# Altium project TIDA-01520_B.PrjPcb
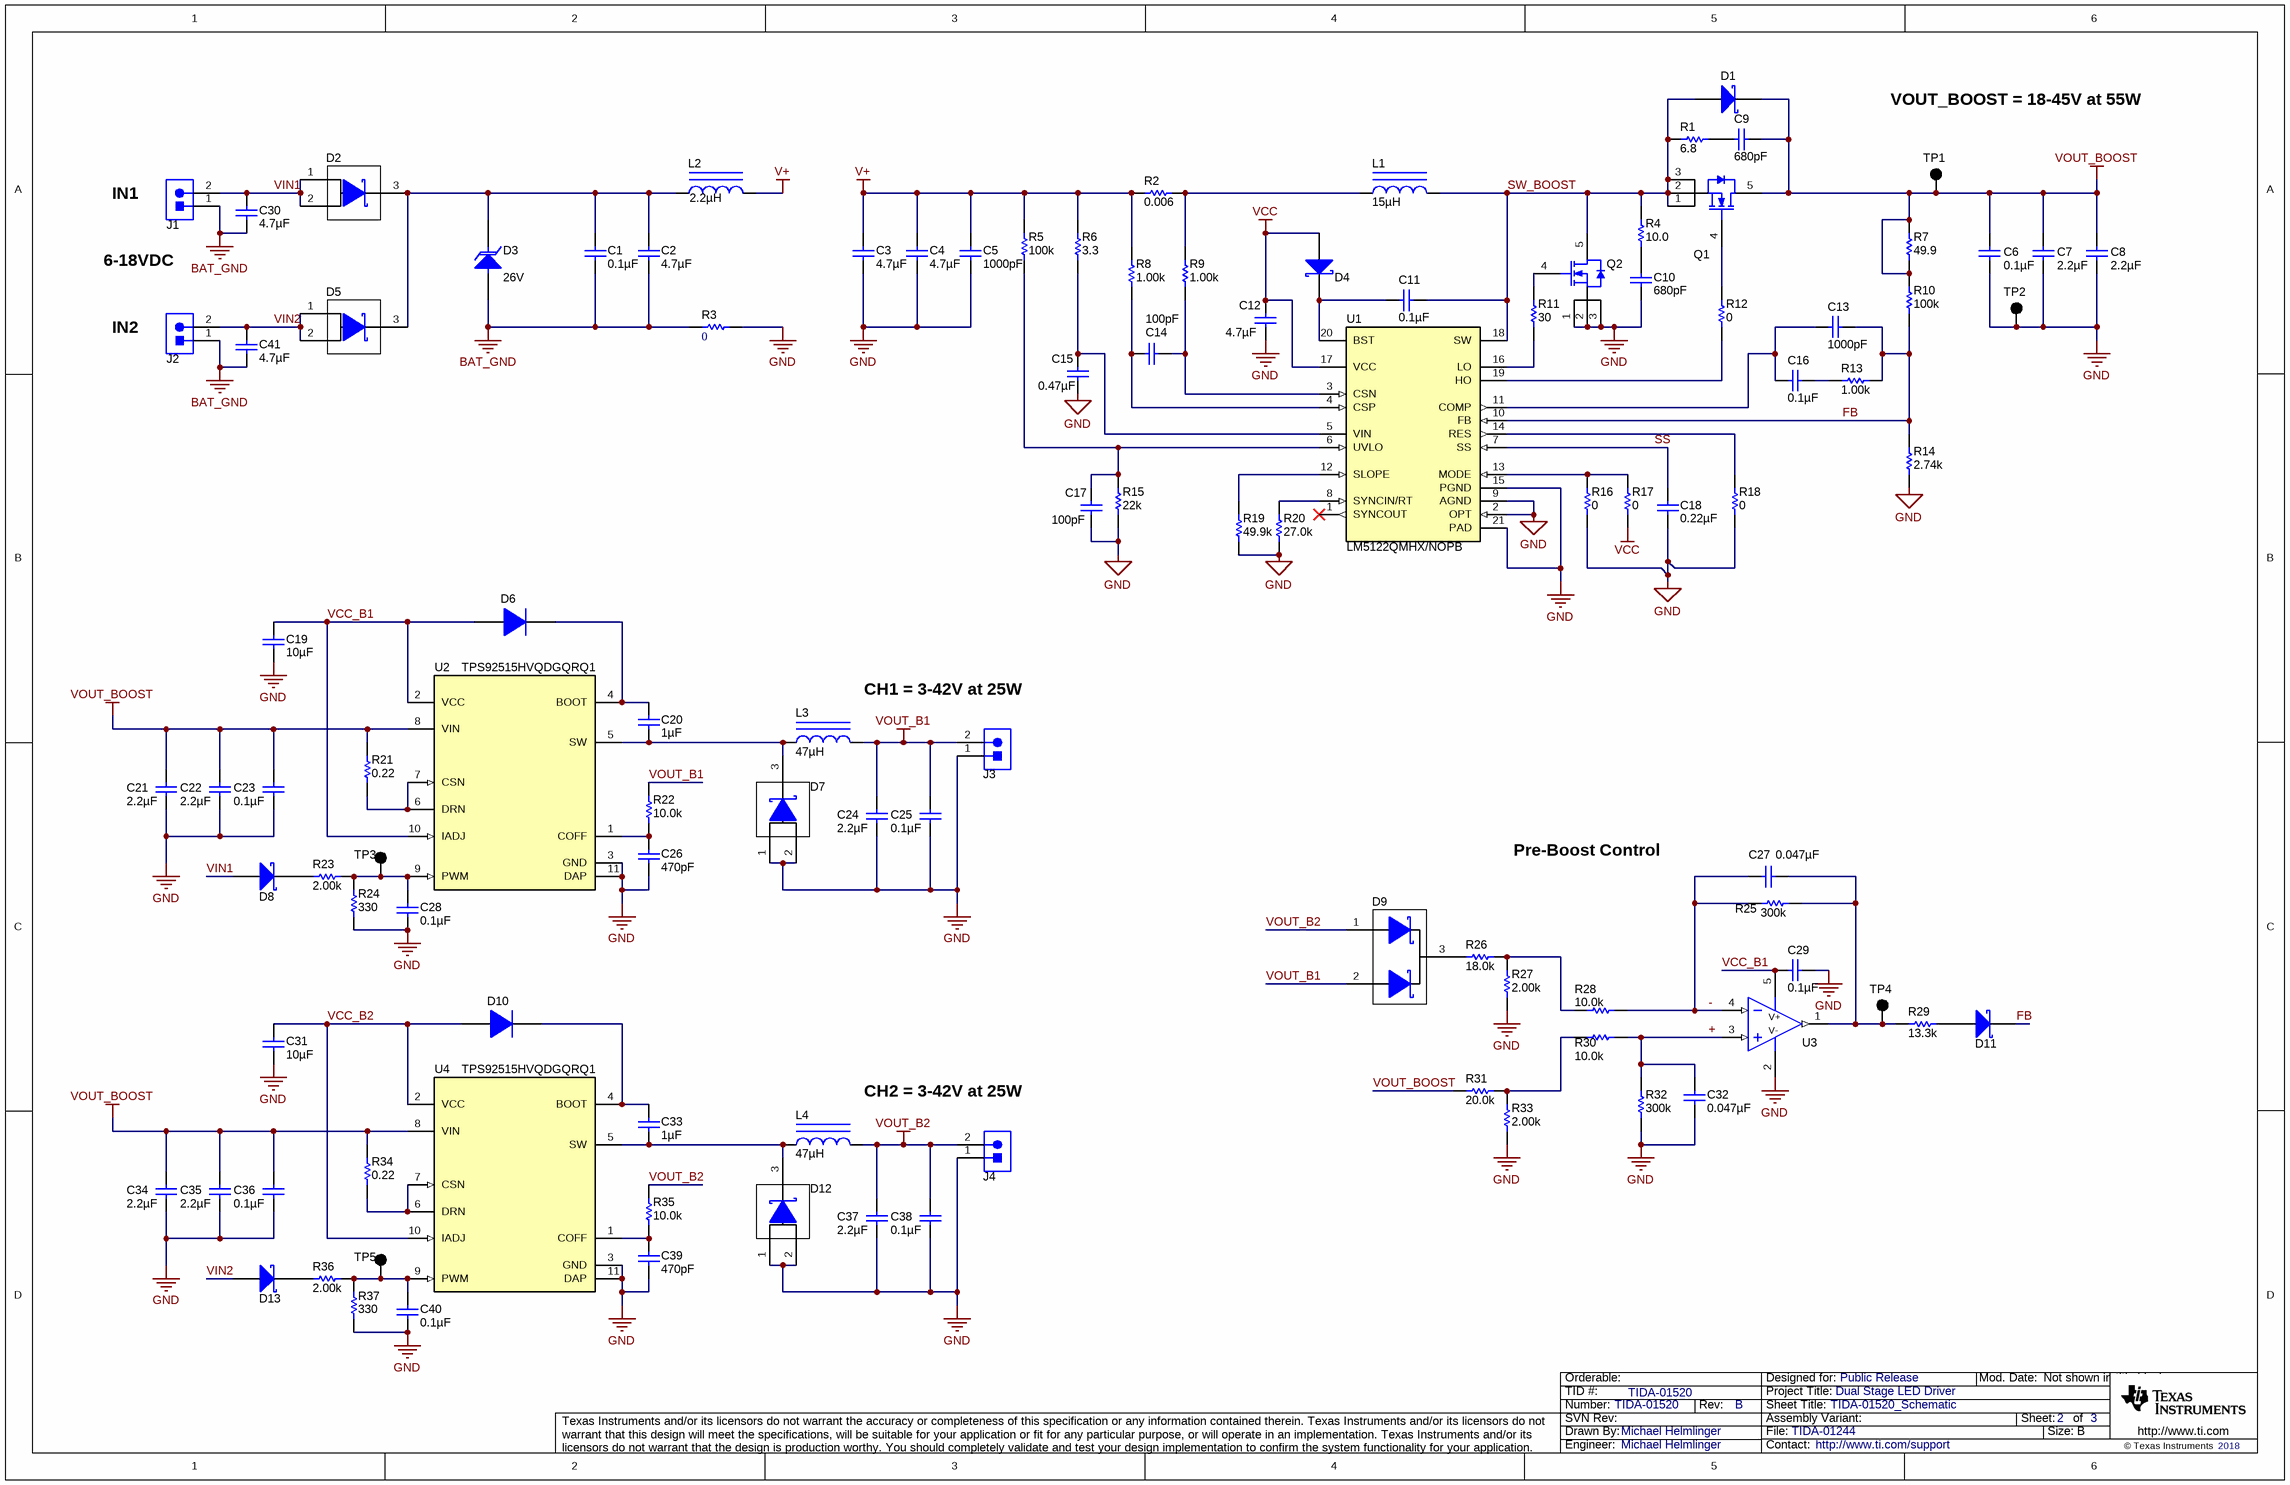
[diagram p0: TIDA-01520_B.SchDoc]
CopyrightYear: 2018; PCB_Layout: Michael Helmlinger; PCB_Rev: B; PRJ_Customer: Public Release; PRJ_Engineer: Michael Helmlinger; PRJ_Number: TIDA-01520; PRJ_Title: Dual Stage LED Driver; SCH_Rev: B; TechSupport: http://www.ti.com/support; TID: TIDA-01520
3 sheets, 119 parts. Net scope: global (net labels, ports and power ports of the same name join across sheets).
Board file: TIDA-01520_B.PcbDoc
Sheets:
  TIDA-01520_B.SchDoc
  TIDA-01520_B_Cover.SchDoc
  TIDA-01520_B_Hardware.SchDoc

## Sheet TIDA-01520_B.SchDoc: TIDA-01520_Schematic
size 431 x 279 mm; Date: Not shown in title block; ApprovedBy: Not shown in title block; CheckedBy: Not shown in title block; Author: Not shown in title block; CompanyName: Not shown in title block; DrawnBy: Michael Helmlinger; Engineer: Not shown in title block; Organization: Not shown in title block; Address1: Not shown in title block; Address2: Not shown in title block; Address3: Not shown in title block; Address4: Not shown in title block; DocumentNumber: 1; Revision: Use project parameter SCH_Rev; SheetNumber: 2; SheetTotal: 3; PageSetup: Record=PageOptions¦CenterHorizontal=True¦CenterVertical=True¦PrintScale=0.94¦XCorrection=1.00¦YCorrection=1.00¦PrintKind=0¦BorderSize=5000000¦LeftOffset=0¦BottomOffset=0¦Orientation=2¦PaperLength=4200¦PaperWidth=2970¦Scale=100¦PaperSource=7¦PrintQuality=600¦MediaType=1¦DitherType=10¦PrintScaleMode=1¦PaperKind=A3¦PaperIndex=8

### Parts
C1  ValueDisplayed: 0.1µF  [0603L]  (hidden comment: CGA3E2X7R1H104K080AA)
C2  ValueDisplayed: 4.7µF  [0805L]  (hidden comment: CGA4J3X5R1H475M125AB)
C3  ValueDisplayed: 4.7µF  [0805L]  (hidden comment: CGA4J3X5R1H475M125AB)
C4  ValueDisplayed: 4.7µF  [0805L]  (hidden comment: CGA4J3X5R1H475M125AB)
C5  ValueDisplayed: 1000pF  [0603L]  (hidden comment: CGA3E2X7R2A102K080AA)
C6  ValueDisplayed: 0.1µF  [0603L]  (hidden comment: CGA3E3X7S2A104K080AB)
C7  ValueDisplayed: 2.2µF  [1206_180]  (hidden comment: CGA5L3X7S2A225K160AB)
C8  ValueDisplayed: 2.2µF  [1206_180]  (hidden comment: CGA5L3X7S2A225K160AB)
C9  ValueDisplayed: 680pF  [0805L]  (hidden comment: GRM216R71E681KA01D)
C10  ValueDisplayed: 680pF  [0805L]  (hidden comment: GRM2165C2A681JA01D)
C11  ValueDisplayed: 0.1µF  [0603L]  (hidden comment: CGA3E2X7R1H104K080AA)
C12  ValueDisplayed: 4.7µF  [0805_HV1]  (hidden comment: GCM21BR71C475KA73L)
C13  ValueDisplayed: 1000pF  [0603L]  (hidden comment: CGA3E2X7R2A102K080AA)
C14  ValueDisplayed: 100pF  [0603L]  (hidden comment: CGA3E2NP01H101J080AA)
C15  ValueDisplayed: 0.47µF  [0603L]  (hidden comment: CGA3E3X7R1H474K080AE)
C16  ValueDisplayed: 0.1µF  [0603L]  (hidden comment: CGA3E2X7R1H104K080AA)
C17  ValueDisplayed: 100pF  [0603L]  (hidden comment: CGA3E2NP01H101J080AA)
C18  ValueDisplayed: 0.22µF  [0603L]  (hidden comment: CGA3E3X8R1E224K080AB)
C19  ValueDisplayed: 10µF  [0603L]  (hidden comment: GRM188R60J106ME84)
C20  ValueDisplayed: 1µF  [0603L]  (hidden comment: CGA3E1X7R1V105K080AC)
C21  ValueDisplayed: 2.2µF  [1206_180]  (hidden comment: CGA5L3X7S2A225K160AB)
C22  ValueDisplayed: 2.2µF  [1206_180]  (hidden comment: CGA5L3X7S2A225K160AB)
C23  ValueDisplayed: 0.1µF  [0603L]  (hidden comment: CGA3E3X7S2A104K080AB)
C24  ValueDisplayed: 2.2µF  [1206_180]  (hidden comment: CGA5L3X7S2A225K160AB)
C25  ValueDisplayed: 0.1µF  [0603L]  (hidden comment: CGA3E3X7S2A104K080AB)
C26  ValueDisplayed: 470pF  [0603L]  (hidden comment: GRM1885C1H471JA01D)
C27  ValueDisplayed: 0.047µF  [0603L]  (hidden comment: CGA3E2X7R1H473K080AA)
C28  ValueDisplayed: 0.1µF  [0603L]  (hidden comment: CGA3E2X7R1H104K080AA)
C29  ValueDisplayed: 0.1µF  [0603S]  (hidden comment: CGA3E2X7R1H104K080AA)
C30  ValueDisplayed: 4.7µF  [0805L]  (hidden comment: CGA4J3X5R1H475M125AB)
C31  ValueDisplayed: 10µF  [0603L]  (hidden comment: GRM188R60J106ME84)
C32  ValueDisplayed: 0.047µF  [0603L]  (hidden comment: CGA3E2X7R1H473K080AA)
C33  ValueDisplayed: 1µF  [0603L]  (hidden comment: CGA3E1X7R1V105K080AC)
C34  ValueDisplayed: 2.2µF  [1206_180]  (hidden comment: CGA5L3X7S2A225K160AB)
C35  ValueDisplayed: 2.2µF  [1206_180]  (hidden comment: CGA5L3X7S2A225K160AB)
C36  ValueDisplayed: 0.1µF  [0603L]  (hidden comment: CGA3E3X7S2A104K080AB)
C37  ValueDisplayed: 2.2µF  [1206_180]  (hidden comment: CGA5L3X7S2A225K160AB)
C38  ValueDisplayed: 0.1µF  [0603L]  (hidden comment: CGA3E3X7S2A104K080AB)
C39  ValueDisplayed: 470pF  [0603L]  (hidden comment: GRM1885C1H471JA01D)
C40  ValueDisplayed: 0.1µF  [0603L]  (hidden comment: CGA3E2X7R1H104K080AA)
C41  ValueDisplayed: 4.7µF  [0805L]  (hidden comment: CGA4J3X5R1H475M125AB)
D1  PMEG6010CEH,115  [SOD-123F]  (value not drawn)
D2  V12P10-M3/86A  [TO-277A]  (value not drawn)
D3  value 26V  [SMC_265]  (hidden comment: TPSMD26A)
D4  PMEG6010CEH,115  [SOD-123F]  (value not drawn)
D5  V12P10-M3/86A  [TO-277A]  (value not drawn)
D6  MMSD4148T1G  [SOD-123]  (value not drawn)
D7  PDS3100Q-13  [PowerDI5]  (value not drawn)
D8  RB520S30,115  [SOD-523]  (value not drawn)
D9  BAS70-05-7-F  [SOT-23]  (value not drawn)
D10  MMSD4148T1G  [SOD-123]  (value not drawn)
D11  RB520S30,115  [SOD-523]  (value not drawn)
D12  PDS3100Q-13  [PowerDI5]  (value not drawn)
D13  RB520S30,115  [SOD-523]  (value not drawn)
J1  1725656  [CONN_1725656]  (value not drawn)
J2  1725656  [CONN_1725656]  (value not drawn)
J3  1725656  [CONN_1725656]  (value not drawn)
J4  1725656  [CONN_1725656]  (value not drawn)
L1  ValueDisplayed: 15µH  [XAL1010]  (hidden comment: XAL1010-153MEB)
L2  ValueDisplayed: 2.2µH  [XAL5030]  (hidden comment: XAL5030-222MEB)
L3  ValueDisplayed: 47µH  [WE-PDA_1260]  (hidden comment: 784771470)
L4  ValueDisplayed: 47µH  [WE-PDA_1260]  (hidden comment: 784771470)
Q1  SQJA60EP  [PowerPAK_SO-8L]  (value not drawn)
Q2  SQJA60EP  [PowerPAK_SO-8L]  (value not drawn)
R1  ValueDisplayed: 6.8  [2010L]  (hidden comment: CRCW20106R80JNEF)
R2  ValueDisplayed: 0.006  [0612]  (hidden comment: PRL1632-R006-F-T1)
R3  ValueDisplayed: 0  [1210L]  (hidden comment: CRCW12100000Z0EA)
R4  ValueDisplayed: 10.0  [1206L]  (hidden comment: PHP01206E10R0BST5)
R5  ValueDisplayed: 100k  [0603L]  (hidden comment: CRCW0603100KJNEA)
R6  ValueDisplayed: 3.3  [0603L]  (hidden comment: CRCW06033R30JNEA)
R7  ValueDisplayed: 49.9  [0805L]  (hidden comment: CRCW080549R9FKEA)
R8  ValueDisplayed: 1.00k  [0603L]  (hidden comment: CRCW06031K00FKEA)
R9  ValueDisplayed: 1.00k  [0603L]  (hidden comment: CRCW06031K00FKEA)
R10  ValueDisplayed: 100k  [0603L]  (hidden comment: CRCW0603100KFKEA)
R11  ValueDisplayed: 30  [0603L]  (hidden comment: CRCW060330R0JNEA)
R12  ValueDisplayed: 0  [0603L]  (hidden comment: CRCW06030000Z0EA)
R13  ValueDisplayed: 1.00k  [0603L]  (hidden comment: CRCW06031K00FKEA)
R14  ValueDisplayed: 2.74k  [0603L]  (hidden comment: CRCW06032K74FKEA)
R15  ValueDisplayed: 22k  [0603L]  (hidden comment: CRCW060322K0JNEA)
R16  ValueDisplayed: 0  [0603L]  (hidden comment: CRCW06030000Z0EA)
R17  ValueDisplayed: 0  [0603L]  (hidden comment: CRCW06030000Z0EA)
R18  ValueDisplayed: 0  [0603L]  (hidden comment: CRCW06030000Z0EA)
R19  ValueDisplayed: 49.9k  [0603L]  (hidden comment: CRCW060349K9FKEA)
R20  ValueDisplayed: 27.0k  [0603L]  (hidden comment: RC0603FR-0727KL)
R21  ValueDisplayed: 0.22  [0805L]  (hidden comment: ERJ-6RQFR22V)
R22  ValueDisplayed: 10.0k  [0603L]  (hidden comment: CRCW060310K0FKEA)
R23  ValueDisplayed: 2.00k  [0603L]  (hidden comment: CRCW06032K00FKEA)
R24  ValueDisplayed: 330  [0603L]  (hidden comment: CRCW0603330RJNEA)
R25  ValueDisplayed: 300k  [0603L]  (hidden comment: CRCW0603300KFKEA)
R26  ValueDisplayed: 18.0k  [0603L]  (hidden comment: RC0603FR-0718KL)
R27  ValueDisplayed: 2.00k  [0603L]  (hidden comment: CRCW06032K00FKEA)
R28  ValueDisplayed: 10.0k  [0603L]  (hidden comment: CRCW060310K0FKEA)
R29  ValueDisplayed: 13.3k  [0603L]  (hidden comment: CRCW060313K3FKEA)
R30  ValueDisplayed: 10.0k  [0603L]  (hidden comment: CRCW060310K0FKEA)
R31  ValueDisplayed: 20.0k  [0603L]  (hidden comment: RC0603FR-0720KL)
R32  ValueDisplayed: 300k  [0603L]  (hidden comment: CRCW0603300KFKEA)
R33  ValueDisplayed: 2.00k  [0603L]  (hidden comment: CRCW06032K00FKEA)
R34  ValueDisplayed: 0.22  [0805L]  (hidden comment: ERJ-6RQFR22V)
R35  ValueDisplayed: 10.0k  [0603L]  (hidden comment: CRCW060310K0FKEA)
R36  ValueDisplayed: 2.00k  [0603L]  (hidden comment: CRCW06032K00FKEA)
R37  ValueDisplayed: 330  [0603L]  (hidden comment: CRCW0603330RJNEA)
TP1  5001  [Keystone5001]  (value not drawn)
TP2  5001  [Keystone5001]  (value not drawn)
TP3  5001  [Keystone5001]  (value not drawn)
TP4  5001  [Keystone5001]  (value not drawn)
TP5  5001  [Keystone5001]  (value not drawn)
U1  LM5122QMHX/NOPB  [PWP0020A_N]
U2  TPS92515HVQDGQRQ1  [DGQ0010E_N]
U3  OPA348AQDBVRQ1  [DBV0005A_N]  (value not drawn)
U4  TPS92515HVQDGQRQ1  [DGQ0010E_N]

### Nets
BAT_GND: C1.2 C2.2 C30.2 C41.2 D3.2(A) J1.1 J2.1 R3.1
GND: C3.2 C4.2 C5.2 C6.2 C7.2 C8.2 C10.2 C12.1 C15.2 C17.2 C18.2 C19.2 C21.2 C22.2 C23.2 C24.2 C25.2 C26.2 C28.2 C29.2 C31.2 C32.2 C34.2 C35.2 C36.2 C37.2 C38.2 C39.2 C40.2 D7.1(A) D7.2(A) D12.1(A) D12.2(A) J3.1 J4.1 Q2.1(S) Q2.2(S) Q2.3(S) R3.2 R14.2 R15.1 R16.2 R18.1 R19.1 R20.1 R24.2 R27.1 R32.1 R33.1 R37.2 TP2.1 U1.2(OPT) U1.9(AGND) U1.15(PGND) U1.21(PAD) U2.3(GND) U2.11(DAP) U3.2(V-) U4.3(GND) U4.11(DAP)
V+: C3.1 C4.1 C5.1 L2.2 R2.1 R5.2 R6.2 R8.2
VCC: C12.2 D4.2(A) R17.2 U1.17(VCC)
VOUT_B1: C24.1 C25.1 D9.2(A) J3.2 L3.2 R22.2
VOUT_B2: C37.1 C38.1 D9.1(A) J4.2 L4.2 R35.2
VOUT_BOOST: C6.1 C7.1 C8.1 C9.1 C21.1 C22.1 C23.1 C34.1 C35.1 C36.1 D1.1(K) Q1.5(D) R7.1 R7.2 R10.2 R21.2 R31.2 R34.2 TP1.1 U2.8(VIN) U4.8(VIN)
+: C32.1 R30.2 R32.2 U3.3(IN+)
-: C27.2 R25.1 R28.2 U3.4(IN-)
FB: C13.2 D11.1(K) R10.1 R13.1 R14.1 U1.10(FB)
SS: C18.1 U1.7(SS)
SW_BOOST: C11.2 D1.2(A) L1.2 Q1.1(S) Q1.2(S) Q1.3(S) Q2.5(D) R1.1 R4.2 U1.18(SW)
VCC_B1: C19.1 C29.1 D6.2(A) U2.2(VCC) U2.10(IADJ) U3.5(V+)
VCC_B2: C31.1 D10.2(A) U4.2(VCC) U4.10(IADJ)
VIN1: C30.1 D2.1(A) D2.2(A) D8.2(A) J1.2
VIN2: C41.1 D5.1(A) D5.2(A) D13.2(A) J2.2
NetC1_1: C1.1 C2.1 D2.3(K) D3.1(K) D5.3(K) L2.1
NetC9_2: C9.2 R1.2
NetC10_1: C10.1 R4.1
NetC11_1: C11.1 D4.1(K) U1.20(BST)
NetC13_1: C13.1 C16.1 U1.11(COMP)
NetC14_1: C14.1 R8.1 U1.4(CSP)
NetC14_2: C14.2 R9.1 U1.3(CSN)
NetC15_1: C15.1 R6.1 U1.5(VIN)
NetC16_2: C16.2 R13.2
NetC17_1: C17.1 R5.1 R15.2 U1.6(UVLO)
NetC20_1: C20.1 D6.1(K) U2.4(BOOT)
NetC20_2: C20.2 D7.3(K) L3.1 U2.5(SW)
NetC26_1: C26.1 R22.1 U2.1(COFF)
NetC27_1: C27.1 R25.2 R29.1 TP4.1 U3.1(OUT)
NetC28_1: C28.1 R23.1 R24.1 TP3.1 U2.9(PWM)
NetC33_1: C33.1 D10.1(K) U4.4(BOOT)
NetC33_2: C33.2 D12.3(K) L4.1 U4.5(SW)
NetC39_1: C39.1 R35.1 U4.1(COFF)
NetC40_1: C40.1 R36.1 R37.1 TP5.1 U4.9(PWM)
NetD8_1: D8.1(K) R23.2
NetD9_3: D9.3(K) R26.2
NetD11_2: D11.2(A) R29.2
NetD13_1: D13.1(K) R36.2
NetL1_1: L1.1 R2.2 R9.2
NetQ1_4: Q1.4(G) R12.2
NetQ2_4: Q2.4(G) R11.2
NetR11_1: R11.1 U1.16(LO)
NetR12_1: R12.1 U1.19(HO)
NetR16_1: R16.1 R17.1 U1.13(MODE)
NetR18_2: R18.2 U1.14(RES)
NetR19_2: R19.2 U1.12(SLOPE)
NetR20_2: R20.2 U1.8(SYNCIN/RT)
NetR21_1: R21.1 U2.6(DRN) U2.7(CSN)
NetR26_1: R26.1 R27.2 R28.1
NetR30_1: R30.1 R31.1 R33.2
NetR34_1: R34.1 U4.6(DRN) U4.7(CSN)

Not connected (* = marked no-connect by the designer): U1 1(SYNCOUT)*

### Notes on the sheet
- VOUT_BOOST = 18-45V at 55W
- IN1
- 6-18VDC
- IN2
- (near R15) 100k and 22k results in Vinstart=6.8V and Vhyst=1V
- (near R20) 27k results in 330kHz FSW
- 0.22uF results in 18ms softstart time
- CH1 = 3-42V at 25W
- Pre-Boost Control
- CH2 = 3-42V at 25W

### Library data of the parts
C1 C11 C16 C28 C29 C40 = CGA3E2X7R1H104K080AA: CAP, CERM, 0.1 µF, 50 V,+/- 10%, X7R, AEC-Q200 Grade 1, 0603; Manufacturer: TDK; Polarized: N; CompType: Capacitor; Value: 0.1uF; U/M: EA; Cap_F: 0.0000001; Tolerance_%: 10; ESR_ohm: 0.0296; Value1: 0.0296 ohm; VDC_V: 50; Value2: 50V; IRMS_A: 0.97199; TaMin_C: -55; TaMax_C: 125; Cap_Case: 0603; SizeArea_mm2: 1.28; SizeAreaWB_mm2: 4.68; SizeX_mm: 1.6; SizeY_mm: 0.8; SizeZ_mm: 1; AEC Category: Q200; AEC Qualified: Y; Green_Lifecycle: Active; Green_REACh: Passed
C2-C4 C30 C41 = CGA4J3X5R1H475M125AB: CAP, CERM, 4.7 µF, 50 V,+/- 20%, X5R, AEC-Q200 Grade 3, 0805; Manufacturer: TDK; Polarized: N; CompType: Capacitor; Value: 4.7uF; U/M: EA; Cap_F: 0.0000047; Tolerance_%: 20; VDC_V: 50; Value2: 50V; TaMin_C: -55; TaMax_C: 85; Cap_Case: 0805; SizeArea_mm2: 2.5; SizeAreaWB_mm2: 6.75; SizeX_mm: 2; SizeY_mm: 1.25; SizeZ_mm: 1.45; AEC Category: Q200; AEC Qualified: Y; AEC Grade: 3
C5 C13 = CGA3E2X7R2A102K080AA: CAP, CERM, 1000 pF, 100 V,+/- 10%, X7R, AEC-Q200 Grade 1, 0603; Manufacturer: TDK; Polarized: N; CompType: Capacitor; Value: 1000pF; U/M: EA; Cap_F: 0.000000001; Tolerance_%: 10; ESR_ohm: 1.97137; Value1: 1.97137 ohm; VDC_V: 100; Value2: 100V; IRMS_A: 0.305705; TaMin_C: -55; TaMax_C: 125; Cap_Case: 0603; SizeArea_mm2: 1.28; SizeAreaWB_mm2: 4.68; SizeX_mm: 1.6; SizeY_mm: 0.8; SizeZ_mm: 1; AEC Category: Q200; AEC Qualified: Y; Green_Lifecycle: Active; Green_REACh: Passed
C6 C23 C25 C36 C38 = CGA3E3X7S2A104K080AB: CAP, CERM, 0.1 µF, 100 V,+/- 10%, X7S, AEC-Q200 Grade 1, 0603; Manufacturer: TDK; Polarized: N; CompType: Capacitor; Value: 0.1uF; U/M: EA; Cap_F: 0.0000001; Tolerance_%: 10; ESR_ohm: 0.04959; Value1: 0.04959 ohm; VDC_V: 100; Value2: 100V; IRMS_A: 0.751618; TaMin_C: -55; TaMax_C: 125; Cap_Case: 0603; SizeArea_mm2: 1.28; SizeAreaWB_mm2: 4.68; SizeX_mm: 1.6; SizeY_mm: 0.8; SizeZ_mm: 1; AEC Category: Q200; AEC Qualified: Y
C7 C8 C21 C22 C24 C34 C35 C37 = CGA5L3X7S2A225K160AB: CAP, CERM, 2.2 µF, 100 V, +/- 10%, X7S, AEC-Q200 Grade 1, 1206; Manufacturer: TDK; Polarized: N; CompType: Capacitor; Value: 2.2uF; U/M: EA; Cap_F: 0.0000022; Tolerance_%: 10; ESR_ohm: 0.005718; Value1: 0.005718 ohm; VDC_V: 100; Value2: 100V; IRMS_A: 3.03632; TaMin_C: -55; TaMax_C: 125; SizeArea_mm2: 5.12; SizeAreaWB_mm2: 10.92; SizeX_mm: 3.2; SizeY_mm: 1.6; SizeZ_mm: 1.8; AEC Category: Q200; AEC Qualified: Y; AEC Grade: 1
C9 = GRM216R71E681KA01D: CAP, CERM, 680 pF, 25 V,+/- 10%, X7R, 0805; Manufacturer: MuRata; Polarized: N; CompType: Capacitor; Value: 680pF; U/M: EA; Cap_F: 0.00000000068; Tolerance_%: 10; VDC_V: 25; Value2: 25V; TaMin_C: -55; TaMax_C: 125; Cap_Case: 0805; SizeArea_mm2: 2.5; SizeAreaWB_mm2: 6.75; SizeX_mm: 2; SizeY_mm: 1.25; SizeZ_mm: 1.45; AEC Category: Q200
C10 = GRM2165C2A681JA01D: CAP, CERM, 680 pF, 100 V,+/- 5%, C0G/NP0, 0805; Manufacturer: MuRata; Polarized: N; CompType: Capacitor; Value: 680pF; U/M: EA; Cap_F: 0.00000000068; Tolerance_%: 5; VDC_V: 100; Value2: 100V; TaMin_C: -55; TaMax_C: 125; Cap_Case: 0805; SizeArea_mm2: 2.5; SizeAreaWB_mm2: 6.75; SizeX_mm: 2; SizeY_mm: 1.25; SizeZ_mm: 1.45; AEC Category: Q200
C12 = GCM21BR71C475KA73L: CAP, CERM, 4.7 µF, 16 V, +/- 10%, X7R, AEC-Q200 Grade 1, 0805; Manufacturer: MuRata; Polarized: N; CompType: Capacitor; Value: 4.7uF; U/M: EA; Cap_F: 0.0000047; Tolerance_%: 10; Value1: Unknown; VDC_V: 16; Value2: 16V; TaMin_C: -55; TaMax_C: 125; Cap_Case: 0805; SizeArea_mm2: 2.5; SizeAreaWB_mm2: 6.75; SizeX_mm: 2; SizeY_mm: 1.25; SizeZ_mm: 1.45; AEC Category: Q200; AEC Qualified: Y; AEC Grade: 1
C14 C17 = CGA3E2NP01H101J080AA: CAP, CERM, 100 pF, 50 V, +/- 5%, C0G/NP0, AEC-Q200 Grade 0, 0603; Manufacturer: TDK; Polarized: N; CompType: Capacitor; Value: 100pF; U/M: EA; Cap_F: 0.0000000001; Tolerance_%: 5; Value1: Unknown; VDC_V: 50; Value2: 50V; TaMin_C: -55; TaMax_C: 150; Cap_Case: 0603; SizeArea_mm2: 1.28; SizeAreaWB_mm2: 4.68; SizeX_mm: 1.6; SizeY_mm: 0.8; SizeZ_mm: 1; AEC Category: Q200; AEC Qualified: Y; AEC Grade: 0
C15 = CGA3E3X7R1H474K080AE: CAP, CERM, 0.47 µF, 50 V, +/- 10%, X7R, AEC-Q200 Grade 1, 0603; Manufacturer: TDK; Polarized: N; CompType: Capacitor; Value: 0.47uF; U/M: EA; Cap_F: 0.00000047; Tolerance_%: 10; Value1: Unknown; VDC_V: 50; Value2: 50V; TaMin_C: -55; TaMax_C: 125; Cap_Case: 0603; SizeArea_mm2: 1.28; SizeAreaWB_mm2: 4.68; SizeX_mm: 1.6; SizeY_mm: 0.8; SizeZ_mm: 1; AEC Category: Q200; AEC Qualified: Y
C18 = CGA3E3X8R1E224K080AB: CAP, CERM, 0.22 µF, 25 V,+/- 10%, X8R, AEC-Q200 Grade 0, 0603; Manufacturer: TDK; Polarized: N; CompType: Capacitor; Value: 0.22uF; U/M: EA; Cap_F: 0.00000022; Tolerance_%: 10; VDC_V: 25; Value2: 25V; TaMin_C: -55; TaMax_C: 150; Cap_Case: 0603; SizeArea_mm2: 1.28; SizeAreaWB_mm2: 4.68; SizeX_mm: 1.6; SizeY_mm: 0.8; SizeZ_mm: 1; AEC Category: Q200; AEC Qualified: Y; AEC Grade: 0
C19 C31 = GRM188R60J106ME84: CAP, CERM, 10 µF, 6.3 V,+/- 20%, X5R, 0603; Manufacturer: MuRata; Polarized: N; CompType: Capacitor; Value: 10uF; U/M: EA; Cap_F: 0.00001; Tolerance_%: 20; VDC_V: 6.3; Value2: 6.3V; TaMin_C: -55; TaMax_C: 85; Cap_Case: 0603; SizeArea_mm2: 1.28; SizeAreaWB_mm2: 4.68; SizeX_mm: 1.6; SizeY_mm: 0.8; SizeZ_mm: 1; AEC Category: Q200; Green_Lifecycle: Active; Green_REACh: Passed
C20 C33 = CGA3E1X7R1V105K080AC: CAP, CERM, 1 µF, 35 V,+/- 10%, X7R, AEC-Q200 Grade 1, 0603; Manufacturer: TDK; Polarized: N; CompType: Capacitor; Value: 1uF; U/M: EA; Cap_F: 0.000001; Tolerance_%: 10; ESR_ohm: 0.005522; Value1: 0.005522 ohm; VDC_V: 35; Value2: 35V; IRMS_A: 2.21617; TaMin_C: -55; TaMax_C: 125; Cap_Case: 0603; SizeArea_mm2: 1.28; SizeAreaWB_mm2: 4.68; SizeX_mm: 1.6; SizeY_mm: 0.8; SizeZ_mm: 1; AEC Category: Q200; AEC Qualified: Y
C26 C39 = GRM1885C1H471JA01D: CAP, CERM, 470 pF, 50 V,+/- 5%, C0G/NP0, 0603; Manufacturer: MuRata; Polarized: N; CompType: Capacitor; Value: 470pF; U/M: EA; Cap_F: 0.00000000047; Tolerance_%: 5; VDC_V: 50; Value2: 50V; TaMin_C: -55; TaMax_C: 125; Cap_Case: 0603; SizeArea_mm2: 1.28; SizeAreaWB_mm2: 4.68; SizeX_mm: 1.6; SizeY_mm: 0.8; SizeZ_mm: 1; AEC Category: Q200; Green_Lifecycle: Active; Green_REACh: Passed
C27 C32 = CGA3E2X7R1H473K080AA: CAP, CERM, 0.047 µF, 50 V,+/- 10%, X7R, AEC-Q200 Grade 1, 0603; Manufacturer: TDK; Polarized: N; CompType: Capacitor; Value: 0.047uF; U/M: EA; Cap_F: 0.000000047; Tolerance_%: 10; ESR_ohm: 0.049007; Value1: 0.049007 ohm; VDC_V: 50; Value2: 50V; IRMS_A: 0.767528; TaMin_C: -55; TaMax_C: 125; Cap_Case: 0603; SizeArea_mm2: 1.28; SizeAreaWB_mm2: 4.68; SizeX_mm: 1.6; SizeY_mm: 0.8; SizeZ_mm: 1; AEC Category: Q200; AEC Qualified: Y
D1 D4 = PMEG6010CEH,115: Diode, Schottky, 60 V, 1 A, SOD-123F; Manufacturer: Nexperia; U/M: EA; Vf_V: 0.57; Value: 60V; Value1: 1A; Value2: 0.57V; Io_A: 1; Vr_V: 60; TJmax_C: 150; SizeAreaWB_mm2: 11.7; SizeArea_mm2: 5.6; SizeX_mm: 3.5; SizeY_mm: 1.6; SizeZ_mm: 1.1; AEC Category: Q101; Green_Lifecycle: Not Set; Green_REACh: Incomplete
D2 D5 = V12P10-M3/86A: Diode, Schottky, 100 V, 12 A, AEC-Q101, TO-277A; Manufacturer: Vishay-Semiconductor; U/M: EA; Vf_V: 0.7; Value: 100V; Value1: 12A; Value2: 0.7V; Io_A: 12; Vr_V: 100; TJmax_C: 150; SizeAreaWB_mm2: 57.375; SizeArea_mm2: 30.875; SizeX_mm: 6.5; SizeY_mm: 4.75; SizeZ_mm: 1.2; AEC Category: Q101; AEC Qualified: Y; Green_Lifecycle: Not Set; Green_REACh: Incomplete
D3 = TPSMD26A: Diode, TVS, Uni, 26 V, 42.1 Vc, AEC-Q101, SMC; Manufacturer: Littelfuse; U/M: EA; Power_W: 6.5; Vr_V: 26; Value1: 6.5W; RJA_CperW: 75; SizeAreaWB_mm2: 78.5757; SizeArea_mm2: 46.8857; SizeX_mm: 7.94; SizeY_mm: 5.905; SizeZ_mm: 2.62; AEC Category: Q101; AEC Qualified: Y
D6 D10 = MMSD4148T1G: Diode, Switching, 100 V, 0.2 A, SOD-123; Manufacturer: ON Semiconductor; U/M: EA; Vf_V: 1; Value: 100V; Value1: 0.2A; Value2: 1V; Io_A: 0.2; Vr_V: 100; TJmax_C: 150; SizeAreaWB_mm2: 13.095; SizeArea_mm2: 6.545; SizeX_mm: 3.85; SizeY_mm: 1.7; SizeZ_mm: 1.35; AEC Category: Q101; Green_Lifecycle: Active; Green_REACh: Passed
D7 D12 = PDS3100Q-13: Diode, Schottky, 100 V, 3 A, AEC-Q101, PowerDI5; Manufacturer: Diodes Inc.; U/M: EA; Vf_V: 0.76; Value: 100V; Value1: 3A; Value2: 0.76V; Io_A: 3; Vr_V: 100; TJmax_C: 150; SizeAreaWB_mm2: 49.56; SizeArea_mm2: 24.96; SizeX_mm: 6.4; SizeY_mm: 3.9; SizeZ_mm: 1.05; AEC Category: Q101; AEC Qualified: Y; Green_Lifecycle: Active; Green_REACh: Passed
D8 D11 D13 = RB520S30,115: Diode, Schottky, 30 V, 0.2 A, SOD-523; Manufacturer: Nexperia; U/M: EA; Vf_V: 0.6; Value: 30V; Value1: 0.2A; Value2: 0.6V; Io_A: 0.2; Vr_V: 30; TJmax_C: 150; SizeAreaWB_mm2: 5.13; SizeArea_mm2: 1.53; SizeX_mm: 1.7; SizeY_mm: 0.9; SizeZ_mm: 0.65; AEC Category: Q101; Green_Lifecycle: Not Set; Green_REACh: Incomplete
D9 = BAS70-05-7-F: Diode, Schottky, 70 V, 0.07 A, SOT-23; Manufacturer: Diodes Inc.; SymbolCreator: a0412235; U/M: EA; Vf_V: 1.7; Value: 70V; Value1: 0.07A; Value2: 1.7V; Io_A: 0.07; Vr_V: 70; SizeAreaWB_mm2: 14; SizeArea_mm2: 7.5; SizeX_mm: 2.5; SizeY_mm: 3; SizeZ_mm: 1.1; AEC Category: Q101; Green_Lifecycle: Not Set; Green_REACh: Incomplete
J1-J4 = 1725656: Terminal Block, 100mil, 2x1, 6A, 63V, TH; Manufacturer: Phoenix Contact; SymbolCreator: a0412235
L1 = XAL1010-153MEB: Inductor, Shielded, Composite, 15 µH, 13.8 A, 0.02 ohm, SMD; Manufacturer: Coilcraft; Value: 15uH; Ind_H: 15.0E-6; Imax_A: 13.8; Irms: 13.8A @ 40C rise; Isat: 15.5A @ 30% inductance drop; DCR_ohm: 0.02; Value2: 13.8A; SizeAreaWB_mm2: 159.6; SizeArea_mm2: 113; SizeX_mm: 11.3; SizeY_mm: 10; AEC Category: Q200; Green_Lifecycle: Not Set; Green_REACh: Incomplete
L2 = XAL5030-222MEB: Inductor, Shielded, Composite, 2.2 µH, 9.2 A, 0.01 ohm, SMD; Manufacturer: Coilcraft; Value: 2.2uH; Ind_H: 2.2E-6; Imax_A: 9.2; Irms: 9.2A @ 40C rise; Isat: 12.9A @ 30% inductance drop; DCR_ohm: 0.01; Value2: 9.2A; SizeAreaWB_mm2: 54.4544; SizeArea_mm2: 28.9344; SizeX_mm: 5.28; SizeY_mm: 5.48; SizeZ_mm: 3.1; AEC Category: Q200; Green_Lifecycle: Not Set; Green_REACh: Incomplete
L3 L4 = 784771470: Inductor, Wirewound, Ferrite, 47 µH, 2.3 A, 0.064 ohm, AEC-Q200 Grade 1, SMD; Manufacturer: Wurth Elektronik; Value: 47uH; Ind_H: 47.0E-6; Imax_A: 2.3; Irms: 2.3A @ 40C rise; Isat: 2.5A @ 10% inductance drop; DCR_ohm: 0.064; Value2: 2.3A; SizeAreaWB_mm2: 196; SizeArea_mm2: 144; SizeX_mm: 12; SizeZ_mm: 6.3; AEC Category: Q200; AEC Qualified: Y; AEC Grade: 1; Green_Lifecycle: Active; Green_REACh: Passed
Q1 Q2 = SQJA60EP: MOSFET, N-CH, 60 V, 30 A, AEC-Q101, PowerPAK_SO-8L; Manufacturer: Vishay-Siliconix; Alternate Manufacturer: None; SymbolCreator: a0412235; U/M: EA; ChType: N; Value: 60V; VdsMax_V: 60; Value1: 0.016 ohm; Rdson45_ohm: 0.016; Value2: 18 nC; QgTyp_nC: 18; Vgs_V: 20; IdsMax_A: 30; SizeAreaWB_mm2: 58.1095; SizeArea_mm2: 31.5495; SizeX_mm: 6.15; SizeY_mm: 5.13; SizeZ_mm: 1.14; AEC Category: Q101; AEC Qualified: Y
R1 = CRCW20106R80JNEF: RES, 6.8, 5%, 0.75 W, AEC-Q200 Grade 0, 2010; Manufacturer: Vishay-Dale; CompType: Resistor; Value: 6.8; Value_Code: 6R80; Tolerance_%: 5; Power_W: 0.75; Value2: 0.75W; VDC_V: 400; TempCo: 200 ppm/C; SizeArea_mm2: 12.5; SizeY_mm: 2.5; SizeZ_mm: 1.66; EIA_Code: E24; U/M: EA; AEC Category: Q200; AEC Qualified: Y; AEC Grade: 0
R2 = PRL1632-R006-F-T1: RES, 0.006, 1%, 1 W, 0612; Manufacturer: Susumu Co Ltd; CompType: Resistor; Value: 0.006; Value_Code: 6L000; Tolerance_%: 1; Value2: 1W; TempCo: 350 ppm/C; SizeArea_mm2: 5.12; SizeAreaWB_mm2: 10.92; SizeX_mm: 1.6; SizeY_mm: 3.2; SizeZ_mm: 0.85; EIA_Code: E96; U/M: EA; AEC Category: Q200; Green_Lifecycle: Active; Green_REACh: Passed
R3 = CRCW12100000Z0EA: RES, 0, 1%, 0.5 W, AEC-Q200 Grade 0, 1210; Manufacturer: Vishay-Dale; CompType: Resistor; Value: 0; Tolerance_%: 1; Power_W: 0.5; Value2: 0.5W; TempCo: ppm/C; SizeArea_mm2: 8; SizeX_mm: 3.2; SizeY_mm: 2.5; SizeZ_mm: 1.35; U/M: EA; AEC Category: Q200; AEC Qualified: Y; SizeAreaWB_mm2: 14.7
R4 = PHP01206E10R0BST5: RES, 10.0, 0.1%, 1 W, 1206; Manufacturer: Vishay-Dale; CompType: Resistor; Value: 10.0; Res_ohm: 10; Value_Code: 10R0; Tolerance_%: 0.1; Power_W: 1; Value2: 1W; VDC_V: 100; TempCo: 25 ppm/C; SizeArea_mm2: 5.12; SizeX_mm: 3.2; SizeY_mm: 1.6; SizeZ_mm: 1.35; EIA_Code: E192; U/M: EA; AEC Category: Q200; Green_Lifecycle: Not Set; Green_REACh: Incomplete
R5 = CRCW0603100KJNEA: RES, 100 k, 5%, 0.1 W, 0603; Manufacturer: Vishay-Dale; CompType: Resistor; Value: 100k; Res_ohm: 100000; Tolerance_%: 5; Power_W: 0.1; Value2: 0.1W; VDC_V: 75; TempCo: 200 ppm/C; SizeArea_mm2: 1.28; SizeX_mm: 1.6; SizeY_mm: 0.8; SizeZ_mm: 1; EIA_Code: E24; U/M: EA; AEC Category: Q200; Green_Lifecycle: Active; Green_REACh: Passed
R6 = CRCW06033R30JNEA: RES, 3.3, 5%, 0.1 W, 0603; Manufacturer: Vishay-Dale; CompType: Resistor; Value: 3.3; Value_Code: 3R30; Tolerance_%: 5; Power_W: 0.1; Value2: 0.1W; VDC_V: 75; TempCo: 200 ppm/C; SizeArea_mm2: 1.28; SizeX_mm: 1.6; SizeY_mm: 0.8; SizeZ_mm: 1; EIA_Code: E24; U/M: EA; AEC Category: Q200; Green_Lifecycle: Active; Green_REACh: Passed
R7 = CRCW080549R9FKEA: RES, 49.9, 1%, 0.125 W, 0805; Manufacturer: Vishay-Dale; CompType: Resistor; Value: 49.9; Value_Code: 49R9; Tolerance_%: 1; Power_W: 0.125; Value2: 0.125W; VDC_V: 150; TempCo: 100 ppm/C; SizeArea_mm2: 2.5; SizeX_mm: 2; SizeY_mm: 1.25; SizeZ_mm: 1.45; EIA_Code: E96; U/M: EA; AEC Category: Q200; Green_Lifecycle: Active; Green_REACh: Passed
R8 R9 R13 = CRCW06031K00FKEA: RES, 1.00 k, 1%, 0.1 W, 0603; Manufacturer: Vishay-Dale; CompType: Resistor; Value: 1.00k; Res_ohm: 1000; Value_Code: 1k00; Tolerance_%: 1; Power_W: 0.1; Value2: 0.1W; VDC_V: 75; TempCo: 100 ppm/C; SizeArea_mm2: 1.28; SizeX_mm: 1.6; SizeY_mm: 0.8; EIA_Code: E96; U/M: EA; AEC Category: Q200; Green_Lifecycle: Active; Green_REACh: Passed
R10 = CRCW0603100KFKEA: RES, 100 k, 1%, 0.1 W, 0603; Manufacturer: Vishay-Dale; CompType: Resistor; Value: 100k; Res_ohm: 100000; Tolerance_%: 1; Power_W: 0.1; Value2: 0.1W; VDC_V: 75; TempCo: 100 ppm/C; SizeArea_mm2: 1.28; SizeX_mm: 1.6; SizeY_mm: 0.8; EIA_Code: E96; U/M: EA; AEC Category: Q200; Green_Lifecycle: Active; Green_REACh: Passed
R11 = CRCW060330R0JNEA: RES, 30, 5%, 0.1 W, 0603; Manufacturer: Vishay-Dale; CompType: Resistor; Value: 30; Value_Code: 30R0; Tolerance_%: 5; Power_W: 0.1; Value2: 0.1W; VDC_V: 75; TempCo: 200 ppm/C; SizeArea_mm2: 1.28; SizeX_mm: 1.6; SizeY_mm: 0.8; SizeZ_mm: 1; EIA_Code: E24; U/M: EA; AEC Category: Q200
R12 R16-R18 = CRCW06030000Z0EA: RES, 0, 5%, 0.1 W, 0603; Manufacturer: Vishay-Dale; CompType: Resistor; Value: 0; Value_Code: 0000; Tolerance_%: 5; Power_W: 0.1; Value2: 0.1W; VDC_V: 75; TempCo: 200 ppm/C; SizeArea_mm2: 1.28; SizeX_mm: 1.6; SizeY_mm: 0.8; SizeZ_mm: 1; EIA_Code: E24; U/M: EA; AEC Category: Q200
R14 = CRCW06032K74FKEA: RES, 2.74 k, 1%, 0.1 W, 0603; Manufacturer: Vishay-Dale; CompType: Resistor; Value: 2.74k; Res_ohm: 2740; Value_Code: 2k74; Tolerance_%: 1; Power_W: 0.1; Value2: 0.1W; VDC_V: 75; TempCo: 100 ppm/C; SizeArea_mm2: 1.28; SizeX_mm: 1.6; SizeY_mm: 0.8; EIA_Code: E96; U/M: EA; AEC Category: Q200; Green_Lifecycle: Active; Green_REACh: Passed
R15 = CRCW060322K0JNEA: RES, 22 k, 5%, 0.1 W, 0603; Manufacturer: Vishay-Dale; CompType: Resistor; Value: 22k; Res_ohm: 22000; Value_Code: 22k0; Tolerance_%: 5; Power_W: 0.1; Value2: 0.1W; VDC_V: 75; TempCo: 200 ppm/C; SizeArea_mm2: 1.28; SizeX_mm: 1.6; SizeY_mm: 0.8; SizeZ_mm: 1; EIA_Code: E24; U/M: EA; AEC Category: Q200; Green_Lifecycle: Active; Green_REACh: Passed
R19 = CRCW060349K9FKEA: RES, 49.9 k, 1%, 0.1 W, 0603; Manufacturer: Vishay-Dale; CompType: Resistor; Value: 49.9k; Res_ohm: 49900; Value_Code: 49k9; Tolerance_%: 1; Power_W: 0.1; Value2: 0.1W; VDC_V: 75; TempCo: 100 ppm/C; SizeArea_mm2: 1.28; SizeX_mm: 1.6; SizeY_mm: 0.8; EIA_Code: E96; U/M: EA; AEC Category: Q200; Green_Lifecycle: Active; Green_REACh: Passed
R20 = RC0603FR-0727KL: RES, 27.0 k, 1%, 0.1 W, 0603; Manufacturer: Yageo America; CompType: Resistor; Value: 27.0k; Res_ohm: 27000; Value_Code: 27k0; Tolerance_%: 1; Power_W: 0.1; Value2: 0.1W; VDC_V: 150; TempCo: 200 ppm/C; SizeArea_mm2: 1.28; SizeX_mm: 1.6; SizeY_mm: 0.8; U/M: EA; AEC Category: Q200; Green_Lifecycle: Active; Green_REACh: Passed
R21 R34 = ERJ-6RQFR22V: RES, 0.22, 1%, 0.125 W, 0805; Manufacturer: Panasonic; CompType: Resistor; Value: 0.22; Value_Code: R220; Tolerance_%: 1; Power_W: 0.125; Value2: 0.125W; TempCo: 250 ppm/C; SizeArea_mm2: 2.5; SizeX_mm: 2; SizeY_mm: 1.25; SizeZ_mm: 1.45; EIA_Code: E96; U/M: EA; AEC Category: Q200
R22 R28 R30 R35 = CRCW060310K0FKEA: RES, 10.0 k, 1%, 0.1 W, 0603; Manufacturer: Vishay-Dale; CompType: Resistor; Value: 10.0k; Res_ohm: 10000; Value_Code: 10k0; Tolerance_%: 1; Power_W: 0.1; Value2: 0.1W; VDC_V: 75; TempCo: 100 ppm/C; SizeArea_mm2: 1.28; SizeX_mm: 1.6; SizeY_mm: 0.8; EIA_Code: E96; U/M: EA; AEC Category: Q200; Green_Lifecycle: Active; Green_REACh: Passed
R23 R27 R33 R36 = CRCW06032K00FKEA: RES, 2.00 k, 1%, 0.1 W, 0603; Manufacturer: Vishay-Dale; CompType: Resistor; Value: 2.00k; Res_ohm: 2000; Value_Code: 2k00; Tolerance_%: 1; Power_W: 0.1; Value2: 0.1W; VDC_V: 75; TempCo: 100 ppm/C; SizeArea_mm2: 1.28; SizeX_mm: 1.6; SizeY_mm: 0.8; EIA_Code: E96; U/M: EA; AEC Category: Q200; Green_Lifecycle: Active; Green_REACh: Passed
R24 R37 = CRCW0603330RJNEA: RES, 330, 5%, 0.1 W, 0603; Manufacturer: Vishay-Dale; CompType: Resistor; Value: 330; Value_Code: 330R; Tolerance_%: 5; Power_W: 0.1; Value2: 0.1W; VDC_V: 75; TempCo: 200 ppm/C; SizeArea_mm2: 1.28; SizeX_mm: 1.6; SizeY_mm: 0.8; SizeZ_mm: 1; EIA_Code: E24; U/M: EA; AEC Category: Q200; Green_Lifecycle: Active; Green_REACh: Passed
R25 R32 = CRCW0603300KFKEA: RES, 300 k, 1%, 0.1 W, 0603; Manufacturer: Vishay-Dale; CompType: Resistor; Value: 300k; Res_ohm: 300000; Tolerance_%: 1; Power_W: 0.1; Value2: 0.1W; TempCo: 100 ppm/C; SizeArea_mm2: 1.28; SizeX_mm: 1.6; SizeY_mm: 0.8; U/M: EA; AEC Category: Q200
R26 = RC0603FR-0718KL: RES, 18.0 k, 1%, 0.1 W, 0603; Manufacturer: Yageo America; CompType: Resistor; Value: 18.0k; Res_ohm: 18000; Value_Code: 18k0; Tolerance_%: 1; Power_W: 0.1; Value2: 0.1W; VDC_V: 150; TempCo: 200 ppm/C; SizeArea_mm2: 1.28; SizeX_mm: 1.6; SizeY_mm: 0.8; U/M: EA; AEC Category: Q200; Green_Lifecycle: Active; Green_REACh: Passed
R29 = CRCW060313K3FKEA: RES, 13.3 k, 1%, 0.1 W, 0603; Manufacturer: Vishay-Dale; CompType: Resistor; Value: 13.3k; Res_ohm: 13300; Value_Code: 13k3; Tolerance_%: 1; Power_W: 0.1; Value2: 0.1W; VDC_V: 75; TempCo: 100 ppm/C; SizeArea_mm2: 1.28; SizeX_mm: 1.6; SizeY_mm: 0.8; EIA_Code: E96; U/M: EA; AEC Category: Q200; Green_Lifecycle: Active; Green_REACh: Passed
R31 = RC0603FR-0720KL: RES, 20.0 k, 1%, 0.1 W, 0603; Manufacturer: Yageo America; CompType: Resistor; Value: 20.0k; Res_ohm: 20000; Value_Code: 20k0; Tolerance_%: 1; Power_W: 0.1; Value2: 0.1W; VDC_V: 150; TempCo: 200 ppm/C; SizeArea_mm2: 1.28; SizeX_mm: 1.6; SizeY_mm: 0.8; EIA_Code: E96; U/M: EA; AEC Category: Q200; Green_Lifecycle: Active; Green_REACh: Passed
TP1-TP5 = 5001: Test Point, Miniature, Black, TH; Manufacturer: Keystone; CompType: Test Point Loop; ContactFinish: Silver; Green_Lifecycle: Active; Green_REACh: Passed
U1 = LM5122QMHX/NOPB: Wide Input Synchronous Boost Controller with Multiple Phase Capability, PWP0020A; Alternate PartNumber: LM5122QMHE/NOPB; Manufacturer: Texas Instruments; SymbolCreator: a0411947; SizeArea_mm2: 41.6; SizeAreaWB_mm2: 71.4; SizeX_mm: 6.4; SizeY_mm: 6.5; SizeZ_mm: 1.2; CompType: IC; U/M: EA
U2 U4 = TPS92515HVQDGQRQ1: 2-A, Buck LED Driver with Integrated N-channel FET, High-Side Current Sense, and Shunt FET PWM Dimming Capability, DGQ0010E (VSSOP-10); Alternate PartNumber: TPS92515HVQDGQTQ1; Manufacturer: Texas Instruments; SymbolCreator: Altium; SizeArea_mm2: 14.64; SizeAreaWB_mm2: 23.52; SizeX_mm: 4.88; SizeY_mm: 3; SizeZ_mm: 1.1; CompType: IC; U/M: EA
U3 = OPA348AQDBVRQ1: Automotive, 1MHz, 45uA, RRIO Single Operational Amplifier, DBV0005A (SOT-23-5); Manufacturer: Texas Instruments; SizeArea_mm2: 8.12; SizeAreaWB_mm2: 14.82; SizeX_mm: 2.8; SizeY_mm: 2.9; SizeZ_mm: 1.45; CompType: IC; U/M: EA

## Sheet TIDA-01520_B_Cover.SchDoc: TIDA-01520_Coversheet
size 431 x 279 mm; Date: Not shown in title block; ApprovedBy: Not shown in title block; CheckedBy: Not shown in title block; Author: Not shown in title block; CompanyName: Not shown in title block; DrawnBy: Michael Helmlinger; Engineer: Not shown in title block; Organization: Not shown in title block; Address1: Not shown in title block; Address2: Not shown in title block; Address3: Not shown in title block; Address4: Not shown in title block; DocumentNumber: 1; Revision: Use project parameter SCH_Rev; SheetNumber: 1; SheetTotal: 3; PageSetup: Record=PageOptions¦CenterHorizontal=True¦CenterVertical=True¦PrintScale=1.00¦XCorrection=1.00¦YCorrection=1.00¦PrintKind=0¦BorderSize=5000000¦LeftOffset=0¦BottomOffset=0¦Orientation=2¦PaperLength=1000¦PaperWidth=1000¦Scale=100¦PaperSource=15¦PrintQuality=-3¦MediaType=1¦DitherType=10¦PrintScaleMode=1¦PaperKind=11x17¦PaperIndex=3
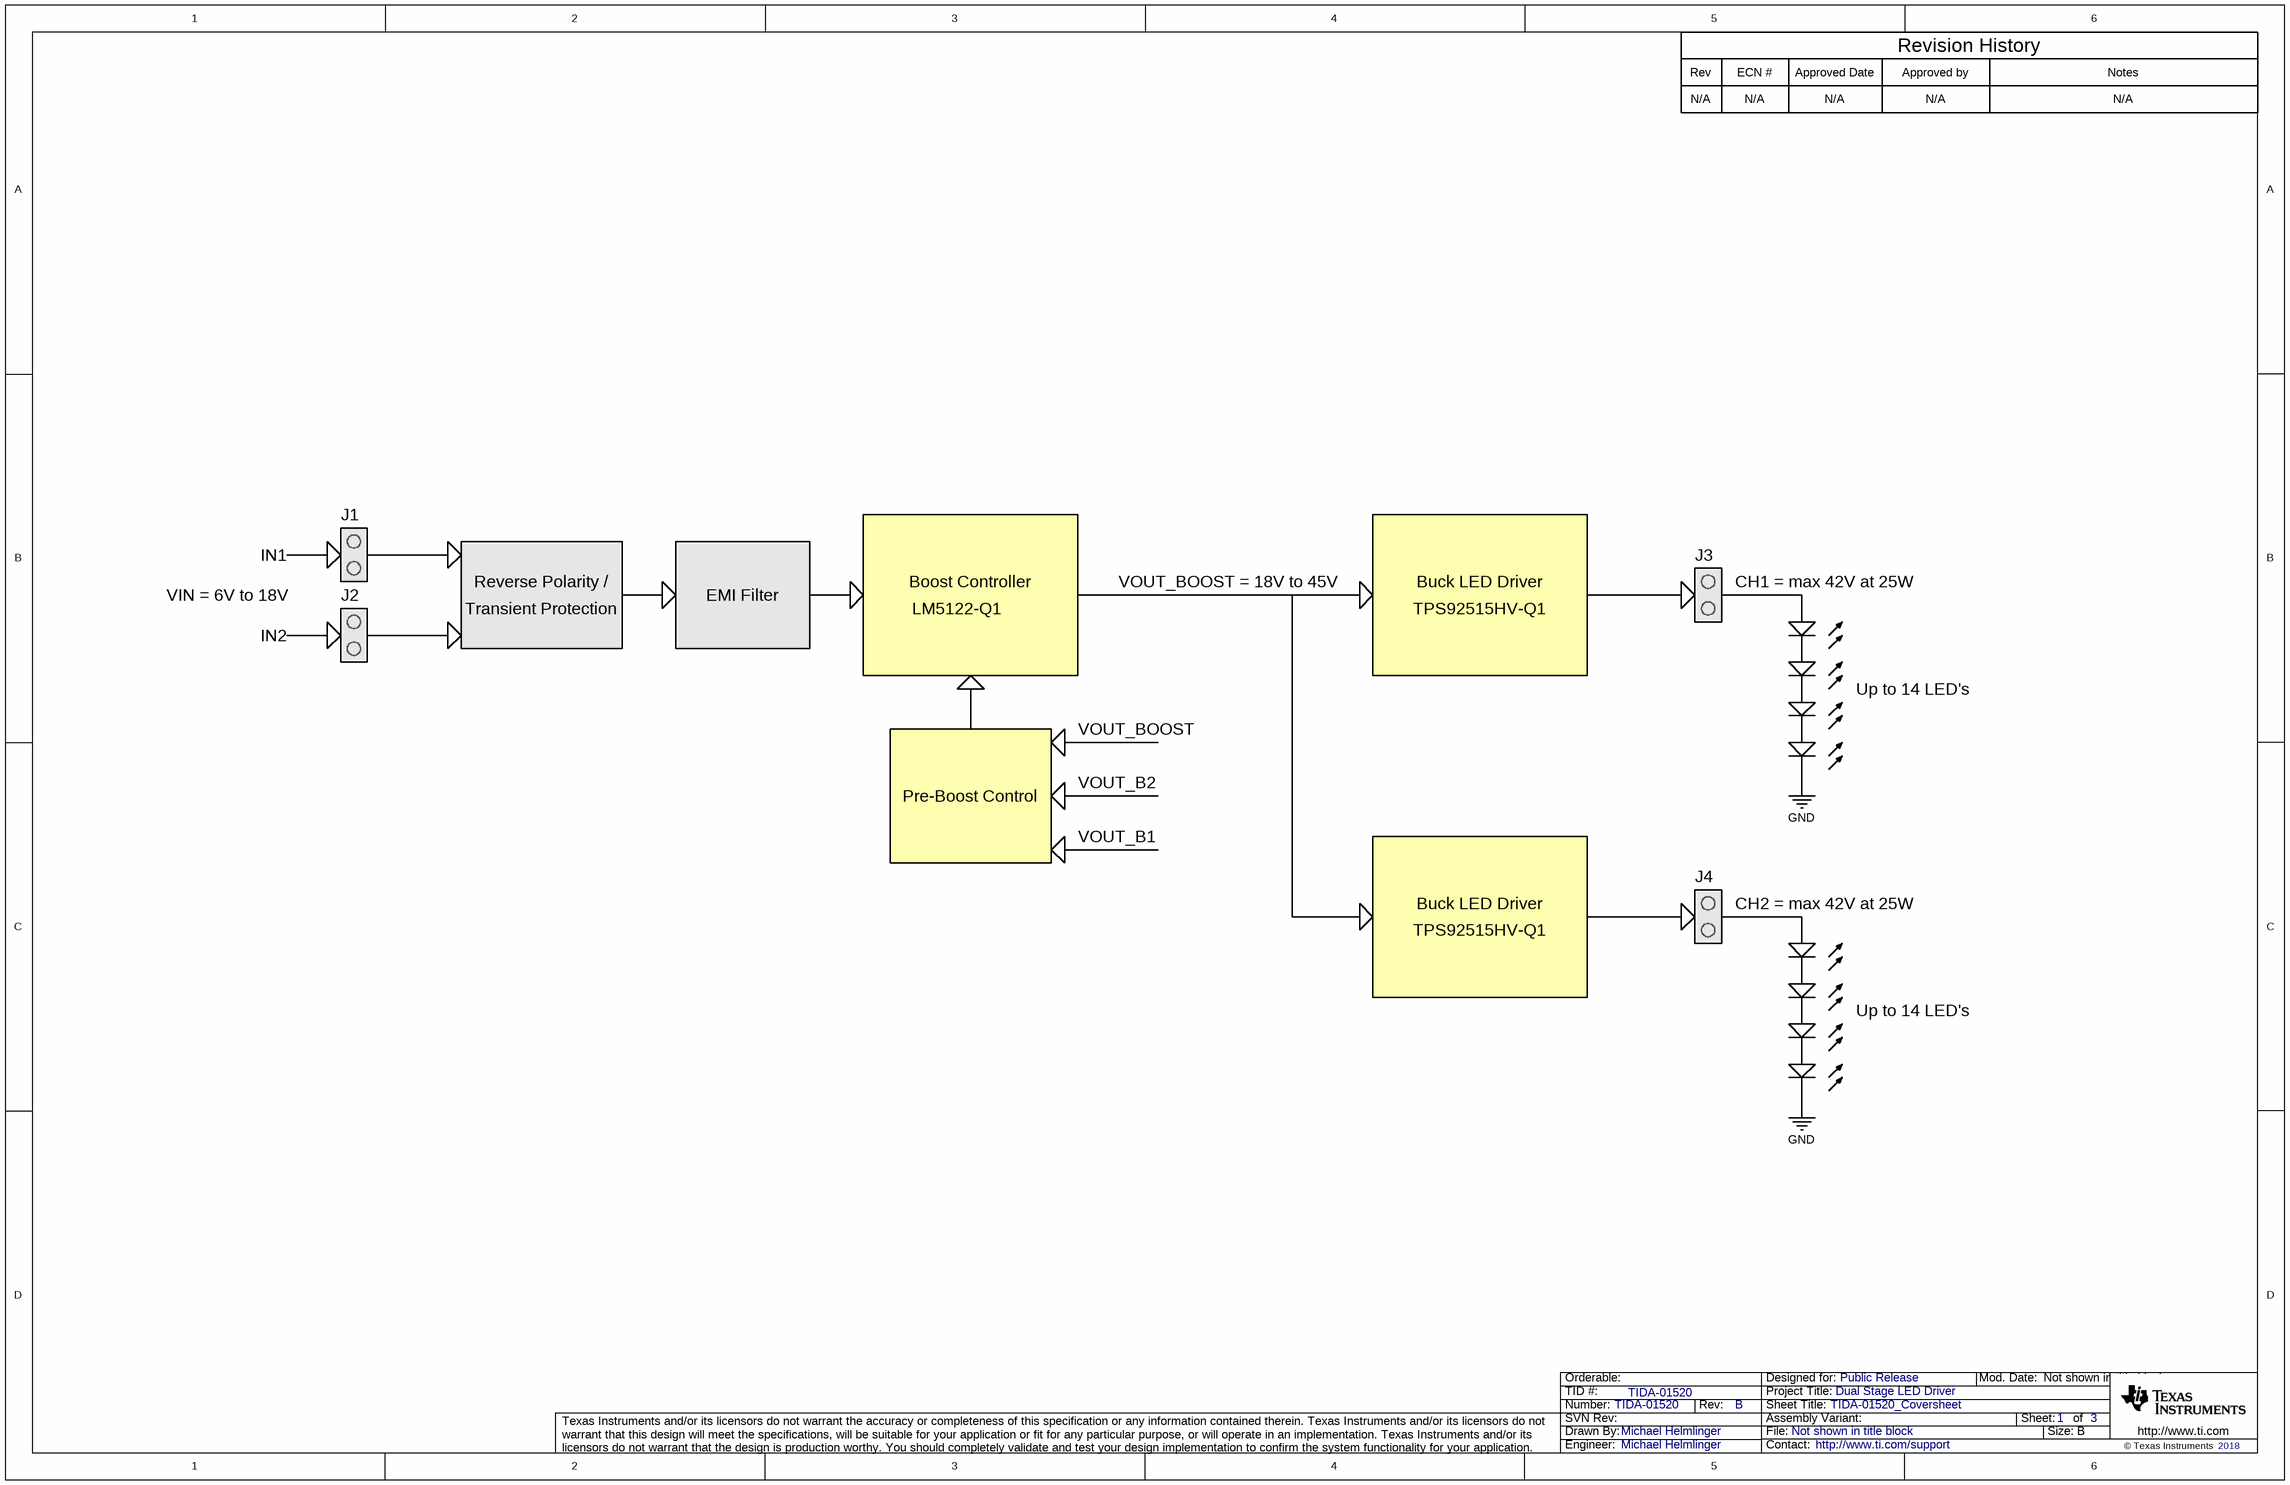
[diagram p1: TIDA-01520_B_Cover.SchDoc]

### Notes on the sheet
- Rev
- N/A
- ECN #
- Approved Date
- Approved by
- Revision History
- Notes
- IN1
- J1
- J3
- VIN = 6V to 18V
- IN2
- J2
- Reverse Polarity /
- Transient Protection
- EMI Filter
- LM5122-Q1
- Boost Controller
- VOUT_BOOST = 18V to 45V
- Buck LED Driver
- TPS92515HV-Q1
- CH1 = max 42V at 25W
- Up to 14 LED's
- VOUT_BOOST
- Pre-Boost Control
- VOUT_B1
- VOUT_B2
- J4
- CH2 = max 42V at 25W
- Labels drawn without touching a wire or pin: GND

## Sheet TIDA-01520_B_Hardware.SchDoc: TIDA-01520_Hardware
size 431 x 279 mm; Date: Not shown in title block; ApprovedBy: Not shown in title block; CheckedBy: Not shown in title block; Author: Not shown in title block; CompanyName: Not shown in title block; DrawnBy: Michael Helmlinger; Engineer: Not shown in title block; Organization: Not shown in title block; Address1: Not shown in title block; Address2: Not shown in title block; Address3: Not shown in title block; Address4: Not shown in title block; DocumentNumber: 1; Revision: Use project parameter SCH_Rev; SheetNumber: 3; SheetTotal: 3; PageSetup: Record=PageOptions¦CenterHorizontal=True¦CenterVertical=True¦PrintScale=1.00¦XCorrection=1.00¦YCorrection=1.00¦PrintKind=0¦BorderSize=5000000¦LeftOffset=0¦BottomOffset=0¦Orientation=2¦PaperLength=1000¦PaperWidth=1000¦Scale=100¦PaperSource=15¦PrintQuality=600¦MediaType=1¦DitherType=10¦PaperKind=Letter¦PrintScaleMode=1
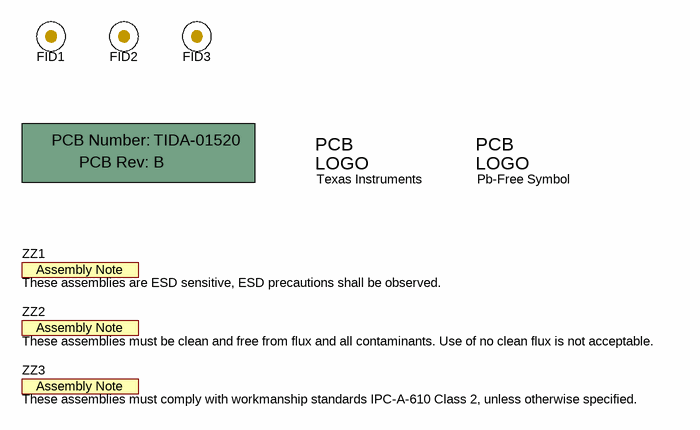
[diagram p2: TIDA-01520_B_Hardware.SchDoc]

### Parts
!PCB1  Printed Circuit Board  (value not drawn)  (mechanical)
FID1  Fiducial  [Fiducial10-20]  (value not drawn)
FID2  Fiducial  [Fiducial10-20]  (value not drawn)
FID3  Fiducial  [Fiducial10-20]  (value not drawn)
Logo1  Texas Instruments  [TI_Stacked_Overlay_Small]  (no BOM)
Logo2  Pb-Free Symbol  [Pb-Free_Overlay_Small]  (no BOM)
ZZ1  These assemblies are ESD sensitive, ESD precautions shall be observed.  [AssemblyNote]  (no BOM)
ZZ2  These assemblies must be clean and free from flux and all contaminants. Use of no clean flux is not acceptable.  [AssemblyNote]  (no BOM)
ZZ3  These assemblies must comply with workmanship standards IPC-A-610 Class 2, unless otherwise specified.  [AssemblyNote]  (no BOM)

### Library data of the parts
!PCB1 = PCB: Manufacturer: Any; PartNumber: TIDA-01520; SymbolCreator: a0412235
FID1-FID3 = Fiducial: Fiducial mark.  There is nothing to buy or mount.; SymbolCreator: codlsc
Logo1 = TI_Logo: Texas Instrument Corporate Signature; SymbolCreator: codlsc
Logo2 = Pb-Free: SymbolCreator: a0412235
ZZ1-ZZ3 = AssemblyNote: SymbolCreator: codlsc

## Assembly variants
001: not fitted C10 FID1 FID2 FID3 R4 R7 R16 TP1 TP2 TP3 TP4 TP5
